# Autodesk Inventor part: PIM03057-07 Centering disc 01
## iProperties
Created: 2007-09
Part Number: PIM03057-07 Centering disc 01
Document SubType Name: Modeling
Designer: WH
Density: 7.86 g/cm^3
Mass: 1532.14 g
Surface Area: 256.088 cm^2
Volume: 194.929 cm^3
Material: 1.0038
Description: Rd.
Author: WH
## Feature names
1. Extrusion1
2. Bohrung1 [Hole]
3. Extrusion2
4. Fase1 [Chamfer]
5. Rundung1 [Fillet]
